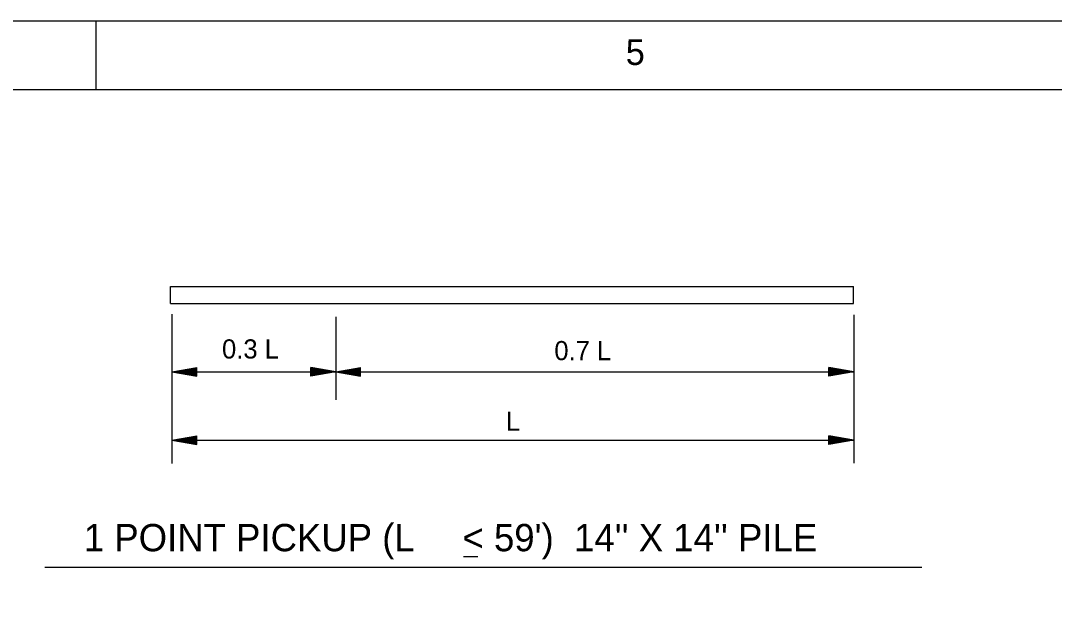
# Model space of a CAD drawing. Extents: x 22369.62 to 22373.29, y 22366.31 to 22369.14.
# Drawn here: x 22372.315 to 22372.945, y 22368.783 to 22369.142 of the extents above; entities that cross this region are included whole.
import ezdxf

# ---------------------------------------------------------------- set-up
doc = ezdxf.new("R2010")
doc.units = 0
for name, color, linetype in [('Level 1', 7, 'Continuous'), ('Level 10', 7, 'Continuous'), ('Level 2', 7, 'Continuous'), ('Level 3', 7, 'Continuous'), ('Level 4', 7, 'Continuous'), ('Level 9', 7, 'Continuous')]:
    doc.layers.add(name, color=color, linetype=linetype)

msp = doc.modelspace()

# ---------------------------------------------------------------- linework, layer by layer
at = {"layer": 'Level 1'}
msp.add_lwpolyline([(22369.6213, 22369.14218), (22373.2867, 22369.14218), (22373.2867, 22366.30818), (22369.6213, 22366.30818)], close=True, dxfattribs=at)
at = {"layer": 'Level 10'}
msp.add_line((22372.3607, 22369.10017), (22372.3607, 22369.14218), dxfattribs=at)
at = {"layer": 'Level 2'}
for p, q in [((22372.40604, 22368.98024), (22372.82254, 22368.98024)), ((22372.40604, 22368.96982), (22372.40604, 22368.98024)), ((22372.82254, 22368.96982), (22372.82254, 22368.98024)), ((22372.40604, 22368.96982), (22372.82254, 22368.96982)), ((22372.58471, 22368.81559), (22372.59343, 22368.81559)), ((22372.32958, 22368.80903), (22372.86413, 22368.80903))]:
    msp.add_line(p, q, dxfattribs=at)
at = {"layer": 'Level 3'}
for p, q in [((22372.40687, 22368.96323), (22372.40687, 22368.8723)), ((22372.50683, 22368.96166), (22372.50683, 22368.91106)), ((22372.82272, 22368.96297), (22372.82272, 22368.87244)), ((22372.40687, 22368.92818), (22372.4221, 22368.93076)), ((22372.40966, 22368.92838), (22372.42144, 22368.93038)), ((22372.42179, 22368.92853), (22372.40966, 22368.92838)), ((22372.41301, 22368.9287), (22372.42108, 22368.93003)), ((22372.42143, 22368.92884), (22372.41301, 22368.9287)), ((22372.41626, 22368.92897), (22372.42077, 22368.92965)), ((22372.42107, 22368.92912), (22372.41626, 22368.92897)), ((22372.42077, 22368.9293), (22372.41936, 22368.92924)), ((22372.42077, 22368.92965), (22372.42077, 22368.9293)), ((22372.42108, 22368.93003), (22372.42107, 22368.92912)), ((22372.42144, 22368.93038), (22372.42143, 22368.92884)), ((22372.42177, 22368.93038), (22372.42179, 22368.92853)), ((22372.4221, 22368.92558), (22372.4221, 22368.93076)), ((22372.49159, 22368.92558), (22372.49159, 22368.93076)), ((22372.50683, 22368.92818), (22372.49159, 22368.93076)), ((22372.49191, 22368.93038), (22372.49191, 22368.92853)), ((22372.49191, 22368.92853), (22372.50404, 22368.92838)), ((22372.50404, 22368.92838), (22372.49226, 22368.93038)), ((22372.49226, 22368.93038), (22372.49228, 22368.92884)), ((22372.49228, 22368.92884), (22372.50069, 22368.9287)), ((22372.50069, 22368.9287), (22372.49262, 22368.93003)), ((22372.49262, 22368.93003), (22372.49262, 22368.92912)), ((22372.49262, 22368.92912), (22372.49745, 22368.92897)), ((22372.49294, 22368.92965), (22372.49293, 22368.9293)), ((22372.49293, 22368.9293), (22372.49432, 22368.92924)), ((22372.49745, 22368.92897), (22372.49294, 22368.92965)), ((22372.50683, 22368.92818), (22372.52206, 22368.93076)), ((22372.50962, 22368.92838), (22372.52139, 22368.93038)), ((22372.52175, 22368.92853), (22372.50962, 22368.92838)), ((22372.51297, 22368.9287), (22372.52104, 22368.93003)), ((22372.52138, 22368.92884), (22372.51297, 22368.9287)), ((22372.51622, 22368.92897), (22372.52073, 22368.92965)), ((22372.52103, 22368.92912), (22372.51622, 22368.92897)), ((22372.52073, 22368.9293), (22372.51933, 22368.92924)), ((22372.52073, 22368.92965), (22372.52073, 22368.9293)), ((22372.52104, 22368.93003), (22372.52103, 22368.92912)), ((22372.52139, 22368.93038), (22372.52138, 22368.92884)), ((22372.52173, 22368.93038), (22372.52175, 22368.92853)), ((22372.52206, 22368.92558), (22372.52206, 22368.93076)), ((22372.80748, 22368.92558), (22372.80748, 22368.93076)), ((22372.82272, 22368.92818), (22372.80748, 22368.93076)), ((22372.80781, 22368.93038), (22372.80779, 22368.92853)), ((22372.80779, 22368.92853), (22372.81992, 22368.92838)), ((22372.81992, 22368.92838), (22372.80814, 22368.93038)), ((22372.80814, 22368.93038), (22372.80815, 22368.92884)), ((22372.80815, 22368.92884), (22372.81656, 22368.9287)), ((22372.81656, 22368.9287), (22372.8085, 22368.93003)), ((22372.8085, 22368.93003), (22372.80851, 22368.92912)), ((22372.80851, 22368.92912), (22372.81332, 22368.92897)), ((22372.80882, 22368.92965), (22372.80881, 22368.9293)), ((22372.80881, 22368.9293), (22372.81021, 22368.92924)), ((22372.81332, 22368.92897), (22372.80882, 22368.92965)), ((22372.40687, 22368.92818), (22372.82272, 22368.92818)), ((22372.40687, 22368.92818), (22372.4221, 22368.92818)), ((22372.40687, 22368.92818), (22372.4221, 22368.92558)), ((22372.42179, 22368.9278), (22372.40966, 22368.92795)), ((22372.40966, 22368.92795), (22372.42144, 22368.92596)), ((22372.41301, 22368.92763), (22372.42108, 22368.9263)), ((22372.42143, 22368.92749), (22372.41301, 22368.92763)), ((22372.41626, 22368.92736), (22372.42077, 22368.92668)), ((22372.42107, 22368.92722), (22372.41626, 22368.92736)), ((22372.42077, 22368.92703), (22372.41936, 22368.92709)), ((22372.42077, 22368.92668), (22372.42077, 22368.92703)), ((22372.42108, 22368.9263), (22372.42107, 22368.92722)), ((22372.42144, 22368.92596), (22372.42143, 22368.92749)), ((22372.42177, 22368.92596), (22372.42179, 22368.9278)), ((22372.50683, 22368.92818), (22372.49159, 22368.92818)), ((22372.50683, 22368.92818), (22372.49159, 22368.92558)), ((22372.49191, 22368.9278), (22372.50404, 22368.92795)), ((22372.49191, 22368.92596), (22372.49191, 22368.9278)), ((22372.50404, 22368.92795), (22372.49226, 22368.92596)), ((22372.49226, 22368.92596), (22372.49228, 22368.92749)), ((22372.49228, 22368.92749), (22372.50069, 22368.92763)), ((22372.50069, 22368.92763), (22372.49262, 22368.9263)), ((22372.49262, 22368.92722), (22372.49745, 22368.92736)), ((22372.49262, 22368.9263), (22372.49262, 22368.92722)), ((22372.49293, 22368.92703), (22372.49432, 22368.92709)), ((22372.49294, 22368.92668), (22372.49293, 22368.92703)), ((22372.49745, 22368.92736), (22372.49294, 22368.92668)), ((22372.50683, 22368.92818), (22372.52206, 22368.92818)), ((22372.50683, 22368.92818), (22372.52206, 22368.92558)), ((22372.52175, 22368.9278), (22372.50962, 22368.92795)), ((22372.50962, 22368.92795), (22372.52139, 22368.92596)), ((22372.51297, 22368.92763), (22372.52104, 22368.9263)), ((22372.52138, 22368.92749), (22372.51297, 22368.92763)), ((22372.51622, 22368.92736), (22372.52073, 22368.92668)), ((22372.52103, 22368.92722), (22372.51622, 22368.92736)), ((22372.52073, 22368.92703), (22372.51933, 22368.92709)), ((22372.52073, 22368.92668), (22372.52073, 22368.92703)), ((22372.52104, 22368.9263), (22372.52103, 22368.92722)), ((22372.52139, 22368.92596), (22372.52138, 22368.92749)), ((22372.52173, 22368.92596), (22372.52175, 22368.9278)), ((22372.82272, 22368.92818), (22372.80748, 22368.92818)), ((22372.82272, 22368.92818), (22372.80748, 22368.92558)), ((22372.80779, 22368.9278), (22372.81992, 22368.92795)), ((22372.80781, 22368.92596), (22372.80779, 22368.9278)), ((22372.81992, 22368.92795), (22372.80814, 22368.92596)), ((22372.80814, 22368.92596), (22372.80815, 22368.92749)), ((22372.80815, 22368.92749), (22372.81656, 22368.92763)), ((22372.81656, 22368.92763), (22372.8085, 22368.9263)), ((22372.8085, 22368.9263), (22372.80851, 22368.92722)), ((22372.80851, 22368.92722), (22372.81332, 22368.92736)), ((22372.80881, 22368.92703), (22372.81021, 22368.92709)), ((22372.80882, 22368.92668), (22372.80881, 22368.92703)), ((22372.81332, 22368.92736), (22372.80882, 22368.92668)), ((22372.40687, 22368.88652), (22372.4221, 22368.8891)), ((22372.40687, 22368.88652), (22372.82272, 22368.88652)), ((22372.40687, 22368.88652), (22372.4221, 22368.88652)), ((22372.40687, 22368.88652), (22372.4221, 22368.88394)), ((22372.40966, 22368.88674), (22372.42144, 22368.88873)), ((22372.42179, 22368.88688), (22372.40966, 22368.88674)), ((22372.42179, 22368.88615), (22372.40966, 22368.8863)), ((22372.40966, 22368.8863), (22372.42144, 22368.88431)), ((22372.41301, 22368.88705), (22372.42108, 22368.88838)), ((22372.42143, 22368.8872), (22372.41301, 22368.88705)), ((22372.41301, 22368.88599), (22372.42108, 22368.88465)), ((22372.42143, 22368.88584), (22372.41301, 22368.88599)), ((22372.41626, 22368.88732), (22372.42077, 22368.88801)), ((22372.42107, 22368.88747), (22372.41626, 22368.88732)), ((22372.41626, 22368.88572), (22372.42077, 22368.88503)), ((22372.42107, 22368.88556), (22372.41626, 22368.88572)), ((22372.42077, 22368.88765), (22372.41936, 22368.88759)), ((22372.42077, 22368.88538), (22372.41936, 22368.88545)), ((22372.42077, 22368.88801), (22372.42077, 22368.88765)), ((22372.42077, 22368.88503), (22372.42077, 22368.88538)), ((22372.42108, 22368.88838), (22372.42107, 22368.88747)), ((22372.42108, 22368.88465), (22372.42107, 22368.88556)), ((22372.42144, 22368.88873), (22372.42143, 22368.8872)), ((22372.42144, 22368.88431), (22372.42143, 22368.88584)), ((22372.42177, 22368.88873), (22372.42179, 22368.88688)), ((22372.42177, 22368.88431), (22372.42179, 22368.88615)), ((22372.4221, 22368.88394), (22372.4221, 22368.8891)), ((22372.80748, 22368.88394), (22372.80748, 22368.8891)), ((22372.82272, 22368.88652), (22372.80748, 22368.8891)), ((22372.82272, 22368.88652), (22372.80748, 22368.88652)), ((22372.82272, 22368.88652), (22372.80748, 22368.88394)), ((22372.80781, 22368.88873), (22372.80779, 22368.88688)), ((22372.80779, 22368.88688), (22372.81992, 22368.88674)), ((22372.80779, 22368.88615), (22372.81992, 22368.8863)), ((22372.80781, 22368.88431), (22372.80779, 22368.88615)), ((22372.81992, 22368.88674), (22372.80814, 22368.88873)), ((22372.80814, 22368.88873), (22372.80815, 22368.8872)), ((22372.81992, 22368.8863), (22372.80814, 22368.88431)), ((22372.80814, 22368.88431), (22372.80815, 22368.88584)), ((22372.80815, 22368.8872), (22372.81656, 22368.88705)), ((22372.80815, 22368.88584), (22372.81656, 22368.88599)), ((22372.81656, 22368.88705), (22372.8085, 22368.88838)), ((22372.8085, 22368.88838), (22372.80851, 22368.88747)), ((22372.81656, 22368.88599), (22372.8085, 22368.88465)), ((22372.8085, 22368.88465), (22372.80851, 22368.88556)), ((22372.80851, 22368.88747), (22372.81332, 22368.88732)), ((22372.80851, 22368.88556), (22372.81332, 22368.88572)), ((22372.80882, 22368.88801), (22372.80881, 22368.88765)), ((22372.80881, 22368.88765), (22372.81021, 22368.88759)), ((22372.80881, 22368.88538), (22372.81021, 22368.88545)), ((22372.80882, 22368.88503), (22372.80881, 22368.88538)), ((22372.81332, 22368.88732), (22372.80882, 22368.88801)), ((22372.81332, 22368.88572), (22372.80882, 22368.88503))]:
    msp.add_line(p, q, dxfattribs=at)
at = {"layer": 'Level 9'}
msp.add_line((22369.7463, 22369.10017), (22373.0157, 22369.10017), dxfattribs=at)

# ---------------------------------------------------------------- texts
at = {"layer": 'Level 1'}
msp.add_text('5', height=0.01561, dxfattribs=at).set_placement((22372.6837, 22369.11518))
at = {"layer": 'Level 2'}
for s, p in [('1 POINT PICKUP (L', (22372.35327, 22368.81877)), ("< 59')  14'' X 14'' PILE", (22372.58415, 22368.81877))]:
    msp.add_text(s, height=0.0166563, dxfattribs=at).set_placement(p)
at = {"layer": 'Level 4'}
for s, height, p in [('0.3 L', 0.011667, (22372.43753, 22368.93626)), ('0.7 L', 0.011656, (22372.64016, 22368.93525)), ('L', 0.01167, (22372.61056, 22368.89226))]:
    msp.add_text(s, height=height, dxfattribs=at).set_placement(p)

doc.saveas('drawing.dxf')
